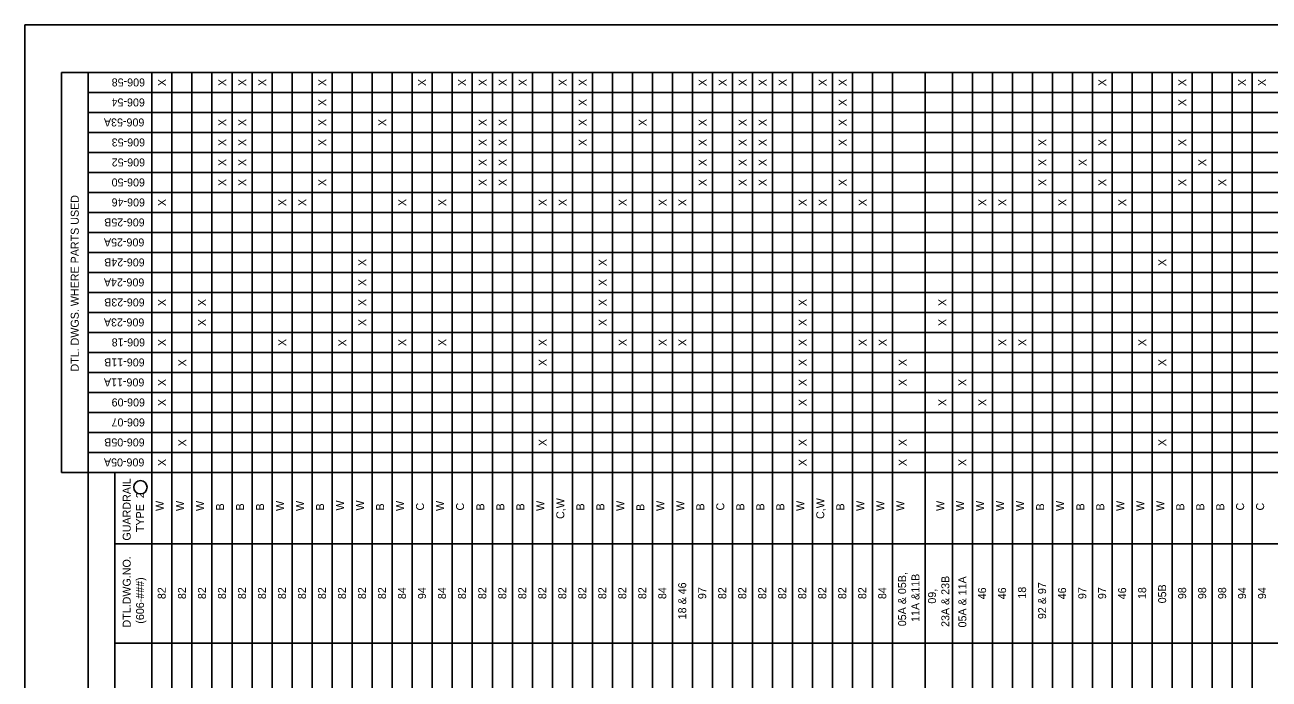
# Model space of a CAD drawing. Extents: x 49991.4 to 50021, y 49987.6 to 50011.4.
# Drawn here: x 49999.38 to 50008.71, y 49994.09 to 49999 of the extents above; entities that cross this region are included whole.
import ezdxf

# ---------------------------------------------------------------- set-up
doc = ezdxf.new("R2010")
doc.units = 0
doc.layers.add('Level 1', color=7, linetype='Continuous')
doc.layers.add('Level 2', color=7, linetype='Continuous')

msp = doc.modelspace()

# ---------------------------------------------------------------- linework, layer by layer
at = {"layer": 'Level 1'}
msp.add_lwpolyline([(49999.3755, 49998.9992), (50016.7421, 49998.9992), (50016.7421, 49987.7988), (49999.3755, 49987.7988)], close=True, dxfattribs=at)
at = {"layer": 'Level 2'}
for p, q in [((49999.6495, 49995.6426), (49999.6495, 49998.6426)), ((50013.2892, 49998.6426), (49999.6495, 49998.6426)), ((49999.8495, 49989.2267), (49999.8495, 49998.6426)), ((50000.3287, 49989.2267), (50000.3287, 49998.6426)), ((50000.4787, 49989.2267), (50000.4787, 49998.6426)), ((50000.6287, 49989.2267), (50000.6287, 49998.6426)), ((50000.7787, 49989.2267), (50000.7787, 49998.6426)), ((50000.9304, 49989.2267), (50000.9304, 49998.6426)), ((50001.0804, 49989.2267), (50001.0804, 49998.6426)), ((50001.2304, 49989.2267), (50001.2304, 49998.6426)), ((50001.3804, 49989.2267), (50001.3804, 49998.6426)), ((50001.5304, 49989.2267), (50001.5304, 49998.6426)), ((50001.6804, 49989.2267), (50001.6804, 49998.6426)), ((50001.8304, 49989.2267), (50001.8304, 49998.6426)), ((50001.9804, 49989.2267), (50001.9804, 49998.6426)), ((50002.1304, 49989.2267), (50002.1304, 49998.6426)), ((50002.2804, 49989.2267), (50002.2804, 49998.6426)), ((50002.4304, 49989.2267), (50002.4304, 49998.6426)), ((50002.5804, 49989.2267), (50002.5804, 49998.6426)), ((50002.7304, 49989.2267), (50002.7304, 49998.6426)), ((50002.8826, 49989.2267), (50002.8826, 49998.6426)), ((50003.0326, 49989.2267), (50003.0326, 49998.6426)), ((50003.1826, 49989.2267), (50003.1826, 49998.6426)), ((50003.3326, 49989.2267), (50003.3326, 49998.6426)), ((50003.4826, 49989.2267), (50003.4826, 49998.6426)), ((50003.6326, 49989.2267), (50003.6326, 49998.6426)), ((50003.7826, 49989.2267), (50003.7826, 49998.6426)), ((50003.9326, 49989.2267), (50003.9326, 49998.6426)), ((50004.0826, 49989.2267), (50004.0826, 49998.6426)), ((50004.2326, 49989.2267), (50004.2326, 49998.6426)), ((50004.3822, 49989.2267), (50004.3822, 49998.6426)), ((50004.5322, 49989.2267), (50004.5322, 49998.6426)), ((50004.6822, 49989.2267), (50004.6822, 49998.6426)), ((50004.8322, 49989.2267), (50004.8322, 49998.6426)), ((50004.9822, 49989.2267), (50004.9822, 49998.6426)), ((50005.1322, 49989.2267), (50005.1322, 49998.6426)), ((50005.2822, 49989.2267), (50005.2822, 49998.6426)), ((50005.4322, 49989.2267), (50005.4322, 49998.6426)), ((50005.5822, 49989.2267), (50005.5822, 49998.6426)), ((50005.7322, 49989.2267), (50005.7322, 49998.6426)), ((50005.8822, 49989.2267), (50005.8822, 49998.6426)), ((50006.1277, 49989.2267), (50006.1277, 49998.6426)), ((50006.3311, 49989.2267), (50006.3311, 49998.6426)), ((50006.4811, 49989.2267), (50006.4811, 49998.6426)), ((50006.6311, 49989.2267), (50006.6311, 49998.6426)), ((50006.7811, 49989.2267), (50006.7811, 49998.6426)), ((50006.9311, 49989.2267), (50006.9311, 49998.6426)), ((50007.0811, 49989.2267), (50007.0811, 49998.6426)), ((50007.2311, 49989.2267), (50007.2311, 49998.6426)), ((50007.3826, 49989.2267), (50007.3826, 49998.6426)), ((50007.5295, 49989.2267), (50007.5295, 49998.6426)), ((50007.6795, 49989.2267), (50007.6795, 49998.6426)), ((50007.8295, 49989.2267), (50007.8295, 49998.6426)), ((50007.9795, 49989.2267), (50007.9795, 49998.6426)), ((50008.1295, 49989.2267), (50008.1295, 49998.6426)), ((50008.2795, 49989.2267), (50008.2795, 49998.6426)), ((50008.4295, 49989.2267), (50008.4295, 49998.6426)), ((50008.5786, 49989.2267), (50008.5786, 49998.6426)), ((49999.8495, 49998.4926), (50013.2892, 49998.4926)), ((49999.8495, 49998.1926), (50013.2892, 49998.1926)), ((50013.2892, 49998.0426), (49999.8495, 49998.0426)), ((49999.8495, 49997.8926), (50013.2892, 49997.8926)), ((50013.2892, 49997.7426), (49999.8495, 49997.7426)), ((49999.8495, 49997.5926), (50013.2892, 49997.5926)), ((50013.2892, 49997.5926), (49999.8495, 49997.5926)), ((49999.8495, 49997.5926), (50013.2892, 49997.5926)), ((50013.2892, 49997.4426), (49999.8495, 49997.4426)), ((49999.8495, 49989.2267), (49999.8495, 49997.4312)), ((49999.8495, 49997.2926), (50013.2892, 49997.2926)), ((50013.2892, 49997.1426), (49999.8495, 49997.1426)), ((49999.8495, 49996.9926), (50013.2892, 49996.9926)), ((50013.2892, 49996.8426), (49999.8495, 49996.8426)), ((49999.8495, 49996.6926), (50013.2892, 49996.6926)), ((50013.2892, 49996.5426), (49999.8495, 49996.5426)), ((49999.8495, 49996.3926), (50013.2892, 49996.3926)), ((50013.2892, 49996.2426), (49999.8495, 49996.2426)), ((49999.8495, 49996.0926), (50013.2892, 49996.0926)), ((50013.2892, 49995.9426), (49999.8495, 49995.9426)), ((49999.8495, 49995.7926), (50013.2892, 49995.7926)), ((50013.2892, 49995.6426), (49999.6495, 49995.6426)), ((50000.0495, 49989.2267), (50000.0495, 49995.6426)), ((50000.0495, 49995.1075), (50013.2892, 49995.1075)), ((50013.2892, 49994.3616), (50000.0495, 49994.3616))]:
    msp.add_line(p, q, dxfattribs=at)
msp.add_lwpolyline([(50013.2892, 49998.3426), (49999.8495, 49998.3426)], dxfattribs=at)
msp.add_circle((50000.2423, 49995.5309), 0.05, dxfattribs=at)

# ---------------------------------------------------------------- texts
for s, rotation, p in [('606-58', 180, (50000.2764, 49998.5976)), ('X', 90, (50000.4337, 49998.5401)), ('X', 90, (50000.8854, 49998.5401)), ('X', 90, (50001.0354, 49998.5401)), ('X', 90, (50001.1854, 49998.5401)), ('X', 90, (50001.6354, 49998.5401)), ('X', 90, (50002.3845, 49998.5401)), ('X', 90, (50002.6845, 49998.5401)), ('X', 90, (50002.8376, 49998.5401)), ('X', 90, (50002.9876, 49998.5401)), ('X', 90, (50003.1376, 49998.5401)), ('X', 90, (50003.4376, 49998.5401)), ('X', 90, (50003.5876, 49998.5401)), ('X', 90, (50004.4872, 49998.5401)), ('X', 90, (50004.6372, 49998.5401)), ('X', 90, (50004.7872, 49998.5401)), ('X', 90, (50004.9372, 49998.5401)), ('X', 90, (50005.0872, 49998.5401)), ('X', 90, (50005.3872, 49998.5401)), ('X', 90, (50005.5372, 49998.5401)), ('X', 90, (50007.4845, 49998.5401)), ('X', 90, (50008.0845, 49998.5401)), ('X', 90, (50008.5336, 49998.5401)), ('X', 90, (50008.6827, 49998.5401)), ('606-54', 180, (50000.2753, 49998.4476)), ('X', 90, (50001.6354, 49998.3901)), ('X', 90, (50003.5876, 49998.3901)), ('X', 90, (50005.5372, 49998.3901)), ('X', 90, (50008.0845, 49998.3901)), ('606-53A', 180, (50000.2717, 49998.2976)), ('X', 90, (50000.8854, 49998.2401)), ('X', 90, (50001.0354, 49998.2401)), ('X', 90, (50001.6354, 49998.2401)), ('X', 90, (50002.0854, 49998.2401)), ('X', 90, (50002.8376, 49998.2401)), ('X', 90, (50002.9876, 49998.2401)), ('X', 90, (50003.5876, 49998.2401)), ('X', 90, (50004.0376, 49998.2401)), ('X', 90, (50004.4872, 49998.2401)), ('X', 90, (50004.7872, 49998.2401)), ('X', 90, (50004.9372, 49998.2401)), ('X', 90, (50005.5372, 49998.2401)), ('606-53', 180, (50000.2766, 49998.1476)), ('X', 90, (50000.8854, 49998.0901)), ('X', 90, (50001.0354, 49998.0901)), ('X', 90, (50001.6354, 49998.0901)), ('X', 90, (50002.8376, 49998.0901)), ('X', 90, (50002.9876, 49998.0901)), ('X', 90, (50003.5876, 49998.0901)), ('X', 90, (50004.4872, 49998.0901)), ('X', 90, (50004.7872, 49998.0901)), ('X', 90, (50004.9372, 49998.0901)), ('X', 90, (50005.5372, 49998.0901)), ('X', 90, (50007.0361, 49998.0901)), ('X', 90, (50007.4845, 49998.0901)), ('X', 90, (50008.0845, 49998.0901)), ('606-52', 180, (50000.2765, 49997.9976)), ('X', 90, (50000.8854, 49997.9401)), ('X', 90, (50001.0354, 49997.9401)), ('X', 90, (50002.8376, 49997.9401)), ('X', 90, (50002.9876, 49997.9401)), ('X', 90, (50004.4872, 49997.9401)), ('X', 90, (50004.7872, 49997.9401)), ('X', 90, (50004.9372, 49997.9401)), ('X', 90, (50007.0361, 49997.9401)), ('X', 90, (50007.3376, 49997.9401)), ('X', 90, (50008.2345, 49997.9401)), ('606-50', 180, (50000.2757, 49997.8476)), ('X', 90, (50000.8854, 49997.7901)), ('X', 90, (50001.0354, 49997.7901)), ('X', 90, (50001.6354, 49997.7901)), ('X', 90, (50002.8376, 49997.7901)), ('X', 90, (50002.9876, 49997.7901)), ('X', 90, (50004.4872, 49997.7901)), ('X', 90, (50004.7872, 49997.7901)), ('X', 90, (50004.9372, 49997.7901)), ('X', 90, (50005.5372, 49997.7901)), ('X', 90, (50007.0361, 49997.7901)), ('X', 90, (50007.4845, 49997.7901)), ('X', 90, (50008.0845, 49997.7901)), ('X', 90, (50008.3845, 49997.7901)), ('DTL. DWGS. WHERE PARTS USED', 90, (49999.7795, 49996.3992)), ('606-46', 180, (50000.2759, 49997.6976)), ('X', 90, (50000.4337, 49997.6401)), ('X', 90, (50001.3354, 49997.6401)), ('X', 90, (50001.4854, 49997.6401)), ('X', 90, (50002.2354, 49997.6401)), ('X', 90, (50002.5354, 49997.6401)), ('X', 90, (50003.2876, 49997.6401)), ('X', 90, (50003.4376, 49997.6401)), ('X', 90, (50003.8876, 49997.6401)), ('X', 90, (50004.1876, 49997.6401)), ('X', 90, (50004.3372, 49997.6401)), ('X', 90, (50005.2372, 49997.6401)), ('X', 90, (50005.3872, 49997.6401)), ('X', 90, (50005.6872, 49997.6401)), ('X', 90, (50006.5861, 49997.6401)), ('X', 90, (50006.7361, 49997.6401)), ('X', 90, (50007.1861, 49997.6401)), ('X', 90, (50007.6345, 49997.6401)), ('606-25B', 180, (50000.2737, 49997.5476)), ('606-25A', 180, (50000.2717, 49997.3976)), ('606-24B', 180, (50000.2737, 49997.2476)), ('X', 90, (50001.9354, 49997.19)), ('X', 90, (50003.7376, 49997.19)), ('X', 90, (50007.9345, 49997.1901)), ('606-24A', 180, (50000.2717, 49997.0976)), ('X', 90, (50001.9354, 49997.04)), ('X', 90, (50003.7376, 49997.04)), ('606-23B', 180, (50000.2737, 49996.9476)), ('X', 90, (50000.4337, 49996.8901)), ('X', 90, (50000.7337, 49996.89)), ('X', 90, (50001.9354, 49996.89)), ('X', 90, (50003.7376, 49996.89)), ('X', 90, (50005.2372, 49996.89)), ('X', 90, (50006.2861, 49996.8902)), ('606-23A', 180, (50000.2717, 49996.7976)), ('X', 90, (50000.7337, 49996.74)), ('X', 90, (50001.9354, 49996.74)), ('X', 90, (50003.7376, 49996.74)), ('X', 90, (50005.2372, 49996.7402)), ('X', 90, (50006.2861, 49996.7402)), ('606-18', 180, (50000.2764, 49996.6476)), ('X', 90, (50000.4337, 49996.5901)), ('X', 90, (50001.3354, 49996.5901)), ('X', 90, (50001.7874, 49996.5881)), ('X', 90, (50002.2354, 49996.5901)), ('X', 90, (50002.5354, 49996.5901)), ('X', 90, (50003.2876, 49996.5901)), ('X', 90, (50003.8876, 49996.5901)), ('X', 90, (50004.1876, 49996.5901)), ('X', 90, (50004.3372, 49996.5901)), ('X', 90, (50005.2372, 49996.5901)), ('X', 90, (50005.6872, 49996.5901)), ('X', 90, (50005.8372, 49996.5901)), ('X', 90, (50006.7361, 49996.5901)), ('X', 90, (50006.8861, 49996.5901)), ('X', 90, (50007.7845, 49996.5901)), ('606-11B', 180, (50000.2737, 49996.4976)), ('X', 90, (50000.5857, 49996.4381)), ('X', 90, (50003.2876, 49996.4401)), ('X', 90, (50005.2372, 49996.4401)), ('X', 90, (50005.9872, 49996.4401)), ('X', 90, (50007.9345, 49996.4401)), ('606-11A', 180, (50000.2717, 49996.3476)), ('X', 90, (50000.4337, 49996.2901)), ('X', 90, (50005.2372, 49996.2901)), ('X', 90, (50005.9872, 49996.2901)), ('X', 90, (50006.4361, 49996.2901)), ('606-09', 180, (50000.2759, 49996.1976)), ('X', 90, (50000.4337, 49996.1401)), ('X', 90, (50005.2372, 49996.1401)), ('X', 90, (50006.2861, 49996.1401)), ('X', 90, (50006.5861, 49996.1401)), ('606-07', 180, (50000.2752, 49996.0476)), ('606-05B', 180, (50000.2737, 49995.8976)), ('X', 90, (50000.5857, 49995.8381)), ('X', 90, (50003.2876, 49995.8401)), ('X', 90, (50005.2372, 49995.8401)), ('X', 90, (50005.9872, 49995.8401)), ('X', 90, (50007.9345, 49995.8401)), ('606-05A', 180, (50000.2717, 49995.7476)), ('X', 90, (50000.4337, 49995.6901)), ('X', 90, (50005.2372, 49995.6901)), ('X', 90, (50005.9872, 49995.6901)), ('X', 90, (50006.4361, 49995.6901)), ('GUARDRAIL', 90, (50000.1691, 49995.1314)), ('TYPE  2', 90, (50000.2691, 49995.1951)), ('W', 90, (50001.7689, 49995.357)), ('W', 90, (50001.9189, 49995.357)), ('C,W', 90, (50003.4209, 49995.2936)), ('C,W', 90, (50005.3705, 49995.2936)), ('W', 90, (50000.4172, 49995.3535)), ('W', 90, (50000.5692, 49995.3535)), ('W', 90, (50000.7192, 49995.3535)), ('B', 90, (50000.8689, 49995.357)), ('B', 90, (50001.0189, 49995.357)), ('B', 90, (50001.1689, 49995.357)), ('W', 90, (50001.3189, 49995.3535)), ('W', 90, (50001.4689, 49995.3535)), ('B', 90, (50001.6189, 49995.357)), ('B', 90, (50002.0689, 49995.357)), ('W', 90, (50002.2189, 49995.3535)), ('C', 90, (50002.3689, 49995.357)), ('W', 90, (50002.5189, 49995.3535)), ('C', 90, (50002.6689, 49995.357)), ('B', 90, (50002.8209, 49995.3571)), ('B', 90, (50002.9709, 49995.3571)), ('B', 90, (50003.1209, 49995.3571)), ('W', 90, (50003.2709, 49995.3536)), ('B', 90, (50003.5709, 49995.3571)), ('B', 90, (50003.7209, 49995.3571)), ('W', 90, (50003.8709, 49995.3536)), ('B', 90, (50004.0209, 49995.3536)), ('W', 90, (50004.1709, 49995.3536)), ('W', 90, (50004.3205, 49995.3536)), ('B', 90, (50004.4705, 49995.3571)), ('C', 90, (50004.6205, 49995.3571)), ('B', 90, (50004.7705, 49995.3571)), ('B', 90, (50004.9205, 49995.3571)), ('B', 90, (50005.0705, 49995.3571)), ('W', 90, (50005.2205, 49995.3536)), ('B', 90, (50005.5205, 49995.3571)), ('W', 90, (50005.6705, 49995.3536)), ('W', 90, (50005.8205, 49995.3536)), ('W', 90, (50005.9705, 49995.3536)), ('W', 90, (50006.2705, 49995.3536)), ('W', 90, (50006.4194, 49995.3536)), ('W', 90, (50006.5694, 49995.3536)), ('W', 90, (50006.7194, 49995.3536)), ('W', 90, (50006.8694, 49995.3536)), ('B', 90, (50007.0194, 49995.3571)), ('W', 90, (50007.1694, 49995.3536)), ('B', 90, (50007.3209, 49995.3571)), ('B', 90, (50007.4699, 49995.3571)), ('W', 90, (50007.6199, 49995.3536)), ('W', 90, (50007.7699, 49995.3536)), ('W', 90, (50007.9199, 49995.3536)), ('B', 90, (50008.0699, 49995.3571)), ('B', 90, (50008.2199, 49995.3571)), ('B', 90, (50008.3699, 49995.3571)), ('C', 90, (50008.519, 49995.3571)), ('C', 90, (50008.669, 49995.3571)), ('DTL.DWG.NO.', 90, (50000.1691, 49994.4792)), ('05A & 05B, ', 90, (50005.9842, 49994.4889)), ('11A &11B', 90, (50006.0842, 49994.5213)), ('(606-###)', 90, (50000.2691, 49994.508)), ('84', 90, (50002.2334, 49994.6925)), ('94', 90, (50002.3834, 49994.6925)), ('84', 90, (50002.5334, 49994.6925)), ('84', 90, (50004.1854, 49994.6925)), ('18 & 46', 90, (50004.335, 49994.5408)), ('84', 90, (50005.835, 49994.6925)), (' 23A & 23B', 90, (50006.3084, 49994.4612)), ('05A & 11A', 90, (50006.4361, 49994.4799)), ('18', 90, (50006.8839, 49994.6958)), ('92 & 97', 90, (50007.0339, 49994.5425)), ('05B', 90, (50007.9344, 49994.6608)), ('94', 90, (50008.5335, 49994.6925)), ('94', 90, (50008.6835, 49994.6925)), ('82', 90, (50000.4317, 49994.6925)), ('82', 90, (50000.5837, 49994.6925)), ('82', 90, (50000.7337, 49994.6925)), ('82', 90, (50000.8834, 49994.6925)), ('82', 90, (50001.0334, 49994.6925)), ('82', 90, (50001.1834, 49994.6925)), ('82', 90, (50001.3334, 49994.6925)), ('82', 90, (50001.4834, 49994.6925)), ('82', 90, (50001.6334, 49994.6925)), ('82', 90, (50001.7834, 49994.6925)), ('82', 90, (50001.9334, 49994.6925)), ('82', 90, (50002.0834, 49994.6925)), ('82', 90, (50002.6834, 49994.6925)), ('82', 90, (50002.8354, 49994.6925)), ('82', 90, (50002.9854, 49994.6925)), ('82', 90, (50003.1354, 49994.6925)), ('82', 90, (50003.2854, 49994.6925)), ('82', 90, (50003.4354, 49994.6925)), ('82', 90, (50003.5854, 49994.6925)), ('82', 90, (50003.7354, 49994.6925)), ('82', 90, (50003.8854, 49994.6925)), ('82', 90, (50004.0354, 49994.6925)), ('97', 90, (50004.485, 49994.6925)), ('82', 90, (50004.635, 49994.6925)), ('82', 90, (50004.785, 49994.6925)), ('82', 90, (50004.935, 49994.6925)), ('82', 90, (50005.085, 49994.6925)), ('82', 90, (50005.235, 49994.6925)), ('82', 90, (50005.385, 49994.6925)), ('82', 90, (50005.535, 49994.6925)), ('82', 90, (50005.685, 49994.6925)), ('09,', 90, (50006.2084, 49994.6584)), ('46', 90, (50006.5839, 49994.6908)), ('46', 90, (50006.7339, 49994.6908)), ('46', 90, (50007.1839, 49994.6908)), ('97', 90, (50007.3354, 49994.6925)), ('97', 90, (50007.4844, 49994.6925)), ('46', 90, (50007.6344, 49994.6908)), ('18', 90, (50007.7844, 49994.6925)), ('98', 90, (50008.0844, 49994.6925)), ('98', 90, (50008.2344, 49994.6925)), ('98', 90, (50008.3844, 49994.6925))]:
    msp.add_text(s, height=0.06, rotation=rotation, dxfattribs=at).set_placement(p)

doc.saveas('drawing.dxf')
